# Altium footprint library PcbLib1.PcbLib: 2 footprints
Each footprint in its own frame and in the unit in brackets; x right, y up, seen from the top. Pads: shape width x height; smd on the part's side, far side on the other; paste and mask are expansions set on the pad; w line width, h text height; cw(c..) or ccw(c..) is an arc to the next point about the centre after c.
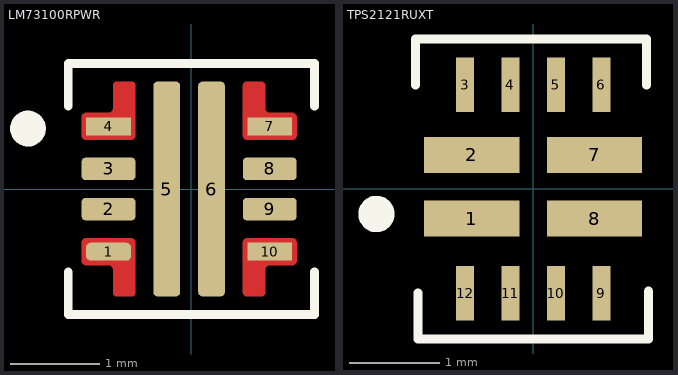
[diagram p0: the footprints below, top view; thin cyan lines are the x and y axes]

## LM73100RPWR [mm] "28.4mV 44.85mΩ VQFN-10-HR(2x2) OR Controllers, Ideal Diodes RoHS"
pads (10):
  rrect50% 0.5x0.2 smd paste-1 mask+0: 1(-0.925,-0.7)
  rrect33% 0.6x0.25 smd mask+0: 2(-0.925,-0.225) 3(-0.925,0.225) 8(0.875,0.225) 9(0.875,-0.225)
  rect 0.5x0.2 smd paste-1 mask+0: 4(-0.925,0.7) 7(0.875,0.7) 10(0.875,-0.7)
  rrect33% 0.3x2.4 smd paste-2 mask+0: 5(-0.275,0) 6(0.225,0)
Top Layer:
  region: 174 vertices and 0 holes, not listed, extent -1.225,-1.2 -0.625,-0.55
  region: 174 vertices and 0 holes, not listed, extent 0.575,-1.2 1.175,-0.55
  region: 174 vertices and 0 holes, not listed, extent 0.575,0.55 1.175,1.2
  region: 174 vertices and 0 holes, not listed, extent -1.225,0.55 -0.625,1.2
Top Overlay:
  circle w0.2: c-1.825,0.675 r0.1
  lines w0.1: -1.375,-0.925 -1.375,-1.4 1.375,-1.4 1.375,-0.925 ; -1.375,0.925 -1.375,1.4 1.375,1.4 1.375,0.925
Top Paste:
  drawing of 8 lines, arcs and shapes, not listed
Top Solder:
  drawing of 10 lines, arcs and shapes, not listed
3D body "step_temp.STEP": height 1, standoff 0, extent -1.025,-1 0.975,1

## TPS2121RUXT [mm] "2.8V~22V 2 VQFN-HR-12(2x2.5) OR Controllers, Ideal Diodes RoHS"
pads (12):
  rect 1.05x0.4 smd paste+0 mask+0.1: 1(-0.675,-0.325) 2(-0.675,0.375) 7(0.675,0.375) 8(0.675,-0.325)
  rect 0.2x0.6 smd paste+0 mask+0.1: 3(-0.75,1.15) 4(-0.25,1.15) 5(0.25,1.15) 6(0.75,1.15) 9(0.75,-1.15) 10(0.25,-1.15) 11(-0.25,-1.15) 12(-0.75,-1.15)
Top Overlay:
  circle w0.2: c-1.725,-0.275 r0.1
  lines w0.1: -1.295,1.143 -1.295,1.651 1.245,1.651 1.245,1.143 ; -1.27,-1.143 -1.27,-1.651 1.27,-1.651 1.27,-1.125
3D body "RUX0012A.stp": height 1, standoff 0, extent -1,-1.25 1,1.25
